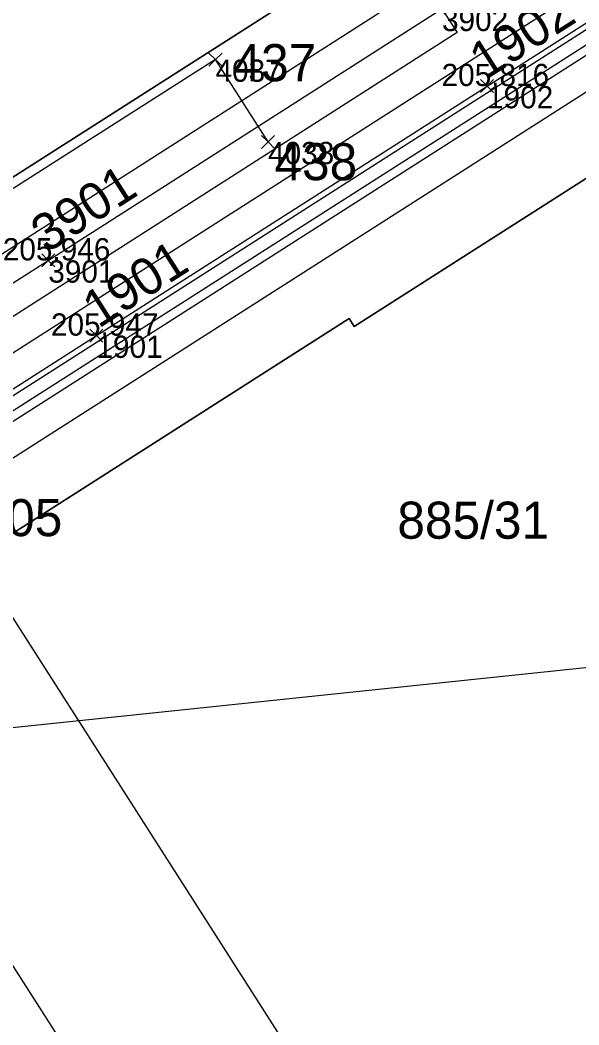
# Model space of a CAD drawing. Extents: x -752184 to -751416, y -1028299 to -1027836.
# Drawn here: x -751675.7 to -751645.5, y -1028071.5 to -1028017.3 of the extents above; entities that cross this region are included whole.
import ezdxf

# ---------------------------------------------------------------- set-up
doc = ezdxf.new("R2010")
doc.units = 0
for name, color, linetype in [('_SO 201 Nástupiště - Přesunutá', 7, 'Continuous'), ('SO 201 Osa koleje', 7, 'Continuous'), ('SO 201 Popisy', 7, 'Continuous'), ('SO 201 Vytyčovací body', 7, 'Continuous'), ('SO 401 a 402 Přeložka SSZT a ČDT', 7, 'Continuous'), ('SO 401 a 402 Vytyčovací body', 7, 'Continuous'), ('Vrstva 53', 7, 'Continuous'), ('Vrstva 55', 7, 'Continuous'), ('Vrstva 57', 7, 'Continuous'), ('Vrstva 60', 7, 'Continuous'), ('Vrstva 61', 7, 'Continuous'), ('Vrstva 63', 7, 'Continuous')]:
    doc.layers.add(name, color=color, linetype=linetype)

msp = doc.modelspace()

# ---------------------------------------------------------------- linework, layer by layer
at = {"layer": '_SO 201 Nástupiště - Přesunutá'}
for p, q in [((-751690.026, -1028046.487), (-751567.868, -1027968.369)), ((-751567.232, -1027969.364), (-751689.391, -1028047.481)), ((-751674.155, -1028030.26), (-751652.926, -1028016.685)), ((-751652.926, -1028016.685), (-751652.107, -1028017.965)), ((-751652.107, -1028017.965), (-751691.168, -1028042.944)), ((-751691.987, -1028041.663), (-751674.155, -1028030.26))]:
    msp.add_line(p, q, dxfattribs=at)
msp.add_lwpolyline([(-751690.188, -1028046.234), (-751671.558, -1028034.321), (-751650.497, -1028020.852), (-751629.435, -1028007.384), (-751608.373, -1027993.915), (-751587.311, -1027980.447), (-751568.029, -1027968.117)], dxfattribs=at)
at = {"layer": 'SO 201 Osa koleje'}
for points in [[(-751812.029, -1028122.19), (-751769.905, -1028095.253), (-751753.825, -1028084.97), (-751748.27, -1028081.417), (-751742.714, -1028077.864), (-751712.886, -1028058.79), (-751682.557, -1028039.395), (-751557.444, -1027959.389), (-751515.321, -1027932.452)], [(-751811.363, -1028127.438), (-751769.239, -1028100.501), (-751746.594, -1028086.019), (-751741.482, -1028082.75), (-751736.37, -1028079.481), (-751710.311, -1028062.817), (-751679.982, -1028043.423), (-751627.749, -1028010.021), (-751616.695, -1028002.953), (-751577.545, -1027977.946)], [(-751782.496, -1028097.583), (-751740.372, -1028070.646), (-751715.482, -1028054.729), (-751685.153, -1028035.335), (-751653.819, -1028015.289), (-751611.692, -1027988.358)]]:
    msp.add_lwpolyline(points, dxfattribs=at)
at = {"layer": 'SO 201 Popisy'}
for p, q in [((-751631.497, -1028119.246), (-751678.366, -1028045.95)), ((-751652.477, -1028105.208), (-751686.886, -1028051.398))]:
    msp.add_line(p, q, dxfattribs=at)
at = {"layer": 'SO 201 Vytyčovací body'}
for points in [[(-751650.143, -1028021.206), (-751650.497, -1028020.852), (-751650.851, -1028020.498)], [(-751650.851, -1028021.206), (-751650.497, -1028020.852), (-751650.143, -1028020.498)], [(-751673.801, -1028030.614), (-751674.155, -1028030.26), (-751674.509, -1028029.906)], [(-751674.509, -1028030.614), (-751674.155, -1028030.26), (-751673.801, -1028029.906)], [(-751671.204, -1028034.675), (-751671.558, -1028034.321), (-751671.912, -1028033.967)], [(-751671.912, -1028034.675), (-751671.558, -1028034.321), (-751671.204, -1028033.967)]]:
    msp.add_lwpolyline(points, dxfattribs=at)
at = {"layer": 'SO 401 a 402 Přeložka SSZT a ČDT'}
msp.add_lwpolyline([(-751662.307, -1028023.867), (-751665.138, -1028019.422), (-751690.565, -1028035.638), (-751702.692, -1028029.879), (-751709.463, -1028036.916), (-751727.486, -1028051.339), (-751724.767, -1028054.621), (-751720.688, -1028061.004)], dxfattribs=at)
at = {"layer": 'SO 401 a 402 Vytyčovací body'}
for points in [[(-751664.784, -1028019.776), (-751665.138, -1028019.422), (-751665.492, -1028019.068)], [(-751665.492, -1028019.776), (-751665.138, -1028019.422), (-751664.784, -1028019.068)], [(-751661.953, -1028024.221), (-751662.307, -1028023.867), (-751662.661, -1028023.513)], [(-751662.661, -1028024.221), (-751662.307, -1028023.867), (-751661.953, -1028023.513)]]:
    msp.add_lwpolyline(points, dxfattribs=at)
at = {"layer": 'Vrstva 53'}
for points in [[(-751934.1, -1028186.19), (-751914.9, -1028176.41), (-751903.43, -1028170.23), (-751901.96, -1028169.44), (-751904.77, -1028166.14), (-751893.52, -1028163.47), (-751890.97, -1028163.13), (-751806.75, -1028109.29), (-751808.53, -1028106.05), (-751798.29, -1028099.68), (-751750.57, -1028069.21), (-751709.61, -1028036.63), (-751702.85, -1028029.39), (-751690.7, -1028035.11), (-751634.83, -1027999.42), (-751532.07, -1027933.64), (-751519.82, -1027926.47), (-751506.87, -1027919.58), (-751494.13, -1027913.25), (-751481.54, -1027906.54), (-751469.19, -1027899.14), (-751466.79, -1027897.6)], [(-751462.19, -1027906.18), (-751523.97, -1027945.11), (-751538.82, -1027960.28), (-751554.98, -1027970.94), (-751563.33, -1027976.45), (-751609.72, -1028006.9), (-751600.73, -1028021.25), (-751610.42, -1028027.79), (-751621, -1028034.71), (-751634.07, -1028041.54), (-751644.14, -1028025.2), (-751657.66, -1028033.82), (-751657.93, -1028033.4), (-751685.36, -1028050.92), (-751685.1, -1028051.35)]]:
    msp.add_lwpolyline(points, dxfattribs=at)
at = {"layer": 'Vrstva 55'}
for points in [[(-751469.19, -1027899.14), (-751481.54, -1027906.54), (-751494.13, -1027913.25), (-751506.87, -1027919.58), (-751519.82, -1027926.47), (-751532.07, -1027933.64), (-751634.83, -1027999.42), (-751690.7, -1028035.11), (-751702.85, -1028029.39)], [(-751811.98, -1028131.93), (-751700.39, -1028060.59), (-751700.15, -1028061), (-751685.1, -1028051.35), (-751685.36, -1028050.92), (-751657.93, -1028033.4), (-751657.66, -1028033.82), (-751644.14, -1028025.2)], [(-751597.31, -1028027.06), (-751634.36, -1028051.12), (-751685.04, -1028056.42), (-751698.4, -1028064.61)]]:
    msp.add_lwpolyline(points, dxfattribs=at)
at = {"layer": 'Vrstva 60'}
for p, q in [((-751665.138, -1028019.422), (-751665.138, -1028019.422)), ((-751650.497, -1028020.852), (-751650.497, -1028020.852)), ((-751662.307, -1028023.867), (-751662.307, -1028023.867)), ((-751674.155, -1028030.26), (-751674.155, -1028030.26)), ((-751671.558, -1028034.321), (-751671.558, -1028034.321))]:
    msp.add_line(p, q, dxfattribs=at)
at = {"layer": 'Vrstva 63'}
msp.add_line((-751551.768, -1027958.946), (-751975.841, -1028229.997), dxfattribs=at)

# ---------------------------------------------------------------- texts
at = {"layer": 'SO 201 Vytyčovací body'}
for s, p in [('1902', (-751650.588, -1028020.549)), ('3901', (-751674.232, -1028029.895)), ('1901', (-751671.449, -1028033.962))]:
    msp.add_text(s, height=2, rotation=32.5976, dxfattribs=at).set_placement(p)
msp.add_text('2005', height=2, dxfattribs=at).set_placement((-751679.346, -1028045.144))
at = {"layer": 'SO 401 a 402 Vytyčovací body'}
for s, p in [('437', (-751664.168, -1028020.588)), ('438', (-751661.959, -1028025.931))]:
    msp.add_text(s, height=2, dxfattribs=at).set_placement(p)
at = {"layer": 'Vrstva 57'}
msp.add_text('885/31', height=2, dxfattribs=at).set_placement((-751655.334, -1028045.28))
at = {"layer": 'Vrstva 60'}
for s, p in [('3902', (-751652.926, -1028017.885)), ('4037', (-751665.138, -1028020.622)), ('1902', (-751650.497, -1028022.052)), ('4038', (-751662.307, -1028025.067)), ('3901', (-751674.155, -1028031.46)), ('1901', (-751671.558, -1028035.521))]:
    msp.add_text(s, height=1.2, dxfattribs=at).set_placement(p)
at = {"layer": 'Vrstva 61'}
for s, p in [('205.816', (-751652.949, -1028020.852)), ('205.946', (-751676.607, -1028030.26)), ('205.947', (-751674.01, -1028034.321))]:
    msp.add_text(s, height=1.2, dxfattribs=at).set_placement(p)

doc.saveas('drawing.dxf')
